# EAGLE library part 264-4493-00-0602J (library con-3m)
Zero Insertion Force Socked Source: http://www.3M.com/ehpd
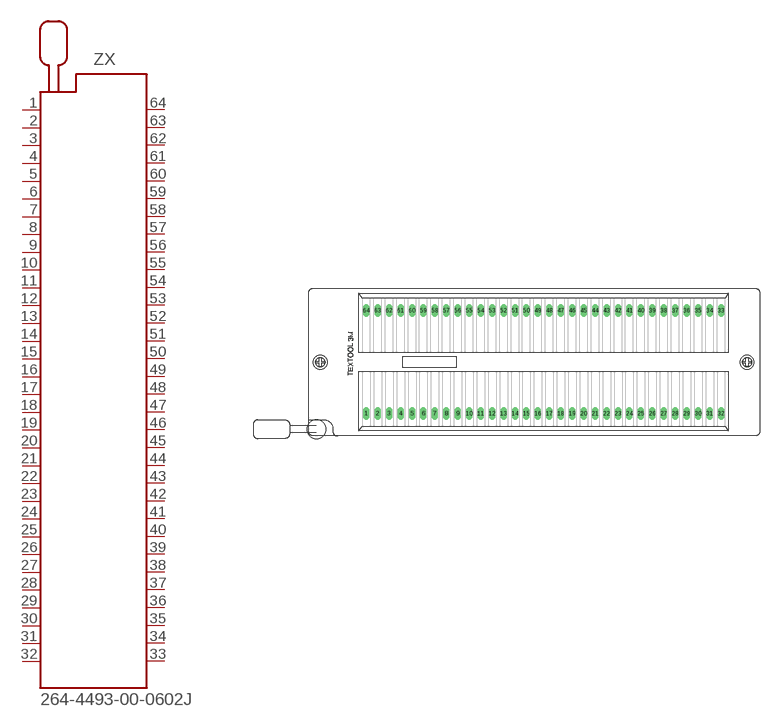
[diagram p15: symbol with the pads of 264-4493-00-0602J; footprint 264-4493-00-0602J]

Designator prefix ZX

## 264-4493-00-0602J (MF: 3M; MPN: 264-4493-00-0602J; OC_FARNELL: 1254441; OC_NEWARK: 85K7875)  [264-4493-00-0602J]
1  1  pas
2  2  pas
3  3  pas
4  4  pas
5  5  pas
6  6  pas
7  7  pas
8  8  pas
9  9  pas
10  10  pas
11  11  pas
12  12  pas
13  13  pas
14  14  pas
15  15  pas
16  16  pas
17  17  pas
18  18  pas
19  19  pas
20  20  pas
21  21  pas
22  22  pas
23  23  pas
24  24  pas
25  25  pas
26  26  pas
27  27  pas
28  28  pas
29  29  pas
30  30  pas
31  31  pas
32  32  pas
33  33  pas
34  34  pas
35  35  pas
36  36  pas
37  37  pas
38  38  pas
39  39  pas
40  40  pas
41  41  pas
42  42  pas
43  43  pas
44  44  pas
45  45  pas
46  46  pas
47  47  pas
48  48  pas
49  49  pas
50  50  pas
51  51  pas
52  52  pas
53  53  pas
54  54  pas
55  55  pas
56  56  pas
57  57  pas
58  58  pas
59  59  pas
60  60  pas
61  61  pas
62  62  pas
63  63  pas
64  64  pas

## Footprint 264-4493-00-0602J (pad centres in mm)
3M TEXTOOL 64 pol. DIP Lever actuated zero insertion force mechanism Hersteller: 3M TEXTOOL Herstellerbez.: 264-4493-00-0602J Farnell Best.-Nr.: 4665478 Source: http://www.3M.com/ehpd
drill 0.9 long: 1 -39.37,-11.43; 2 -36.83,-11.43; 3 -34.29,-11.43; 4 -31.75,-11.43; 5 -29.21,-11.43; 6 -26.67,-11.43; 7 -24.13,-11.43; 8 -21.59,-11.43; 9 -19.05,-11.43; 10 -16.51,-11.43; 11 -13.97,-11.43; 12 -11.43,-11.43; 13 -8.89,-11.43; 14 -6.35,-11.43; 15 -3.81,-11.43; 16 -1.27,-11.43; 17 1.27,-11.43; 18 3.81,-11.43; 19 6.35,-11.43; 20 8.89,-11.43; 21 11.43,-11.43; 22 13.97,-11.43; 23 16.51,-11.43; 24 19.05,-11.43; 25 21.59,-11.43; 26 24.13,-11.43; 27 26.67,-11.43; 28 29.21,-11.43; 29 31.75,-11.43; 30 34.29,-11.43; 31 36.83,-11.43; 32 39.37,-11.43; 33 39.37,11.43; 34 36.83,11.43; 35 34.29,11.43; 36 31.75,11.43; 37 29.21,11.43; 38 26.67,11.43; 39 24.13,11.43; 40 21.59,11.43; 41 19.05,11.43; 42 16.51,11.43; 43 13.97,11.43; 44 11.43,11.43; 45 8.89,11.43; 46 6.35,11.43; 47 3.81,11.43; 48 1.27,11.43; 49 -1.27,11.43; 50 -3.81,11.43; 51 -6.35,11.43; 52 -8.89,11.43; 53 -11.43,11.43; 54 -13.97,11.43; 55 -16.51,11.43; 56 -19.05,11.43; 57 -21.59,11.43; 58 -24.13,11.43; 59 -26.67,11.43; 60 -29.21,11.43; 61 -31.75,11.43; 62 -34.29,11.43; 63 -36.83,11.43; 64 -39.37,11.43
hole 2 at -49.56,0
hole 2 at 45.14,0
